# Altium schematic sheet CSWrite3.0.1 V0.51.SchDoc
size 609 x 431 mm; PageSetup: Record=PageOptions¦CenterHorizontal=True¦CenterVertical=True¦PrintScale=0.38¦XCorrection=1.00¦YCorrection=1.00¦PrintKind=2¦BorderSize=5000000¦LeftOffset=0¦BottomOffset=0¦Orientation=2¦PaperLength=1000¦PaperWidth=1000¦Scale=100¦PaperSource=7¦PrintQuality=-4¦MediaType=1¦DitherType=10¦PaperKind=A4¦PrintScaleMode=1
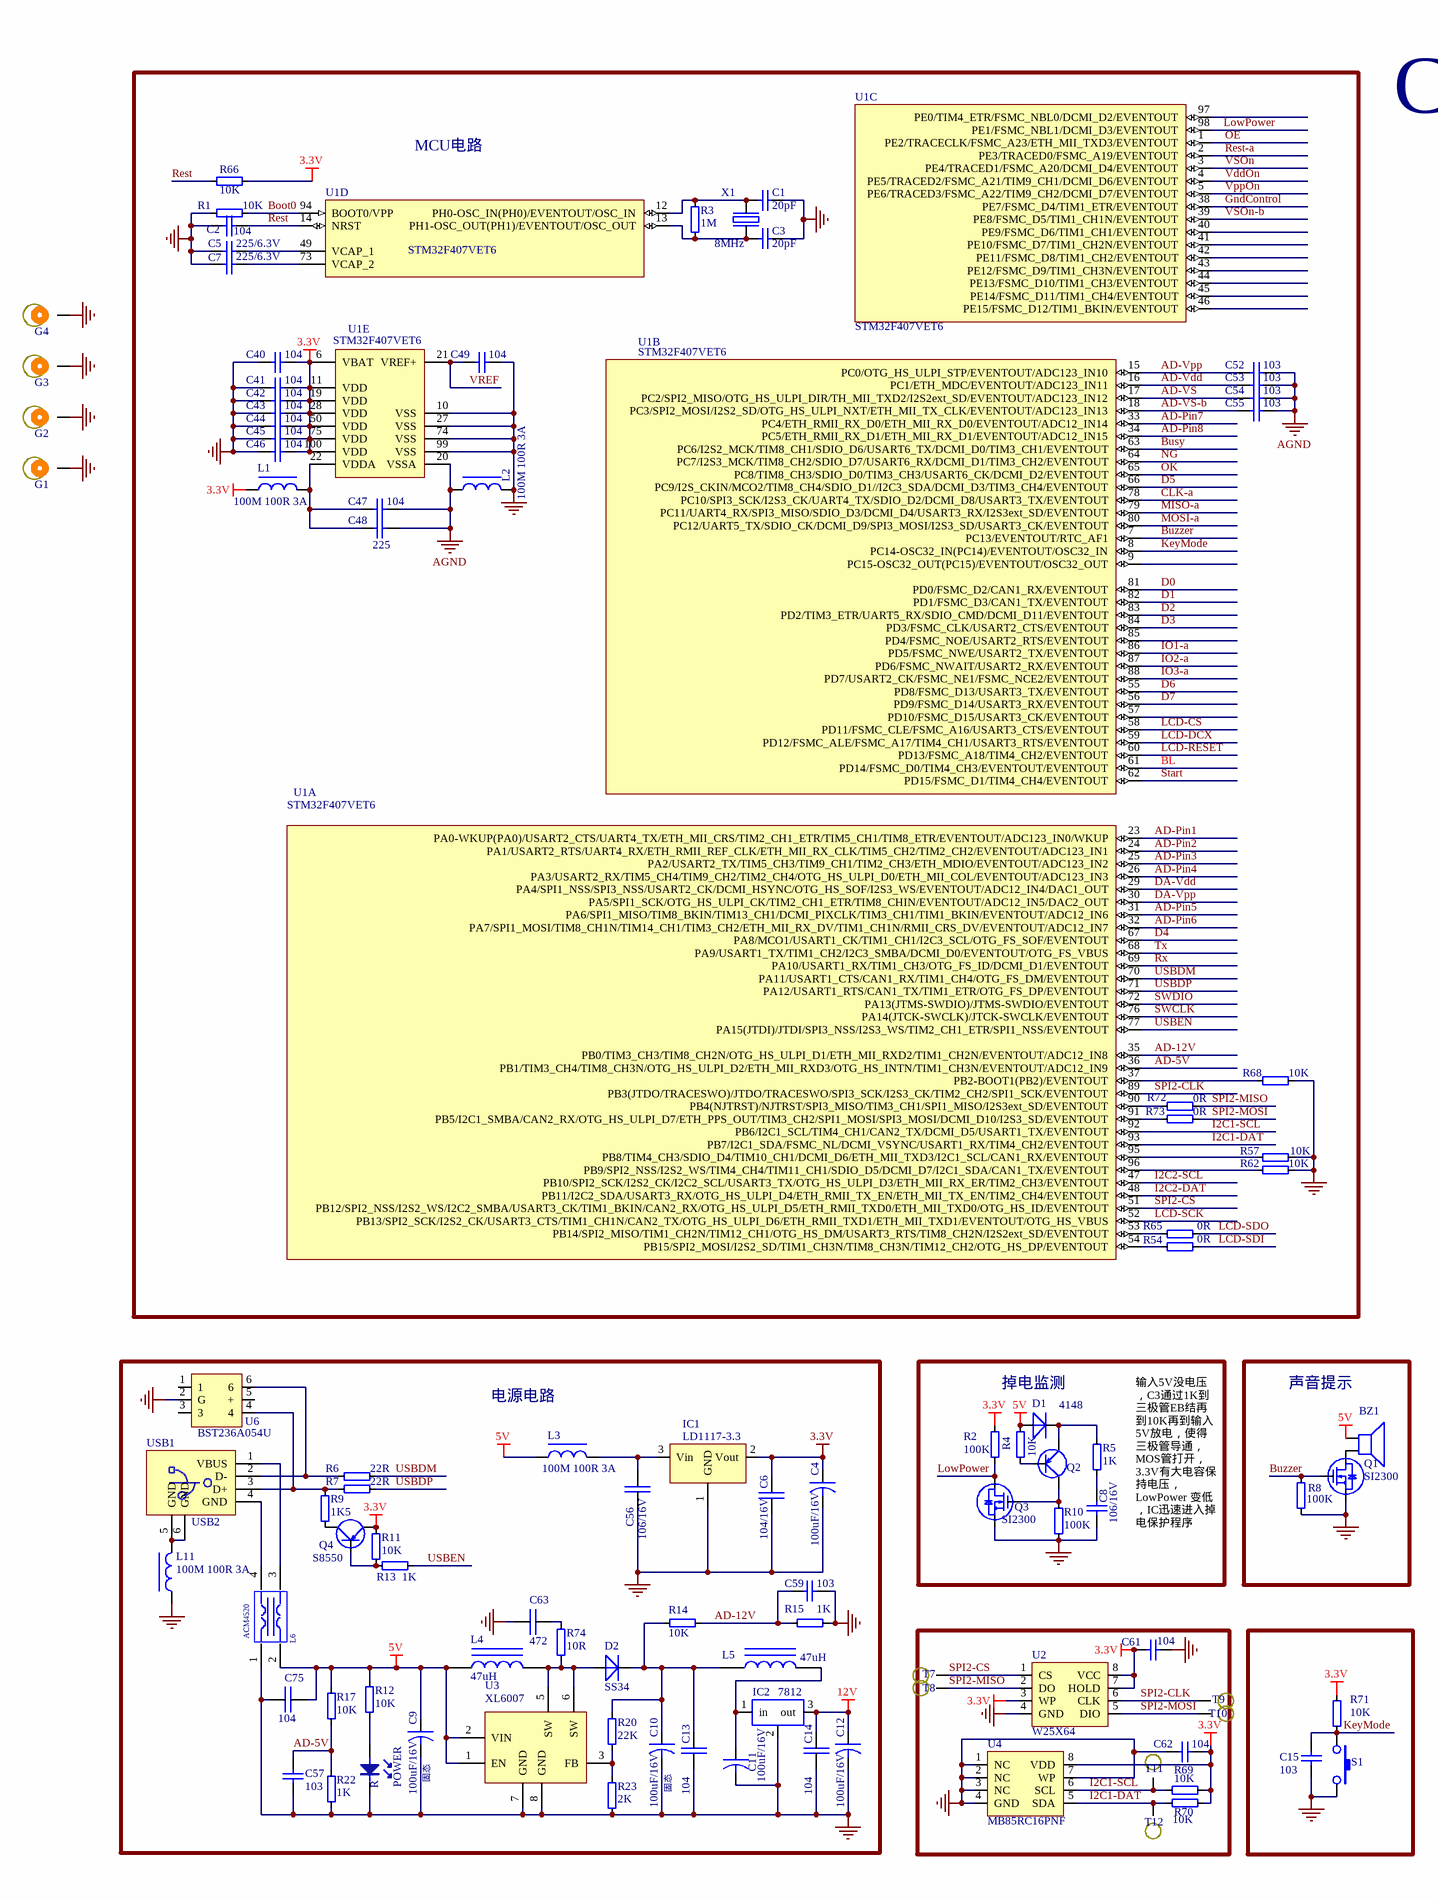
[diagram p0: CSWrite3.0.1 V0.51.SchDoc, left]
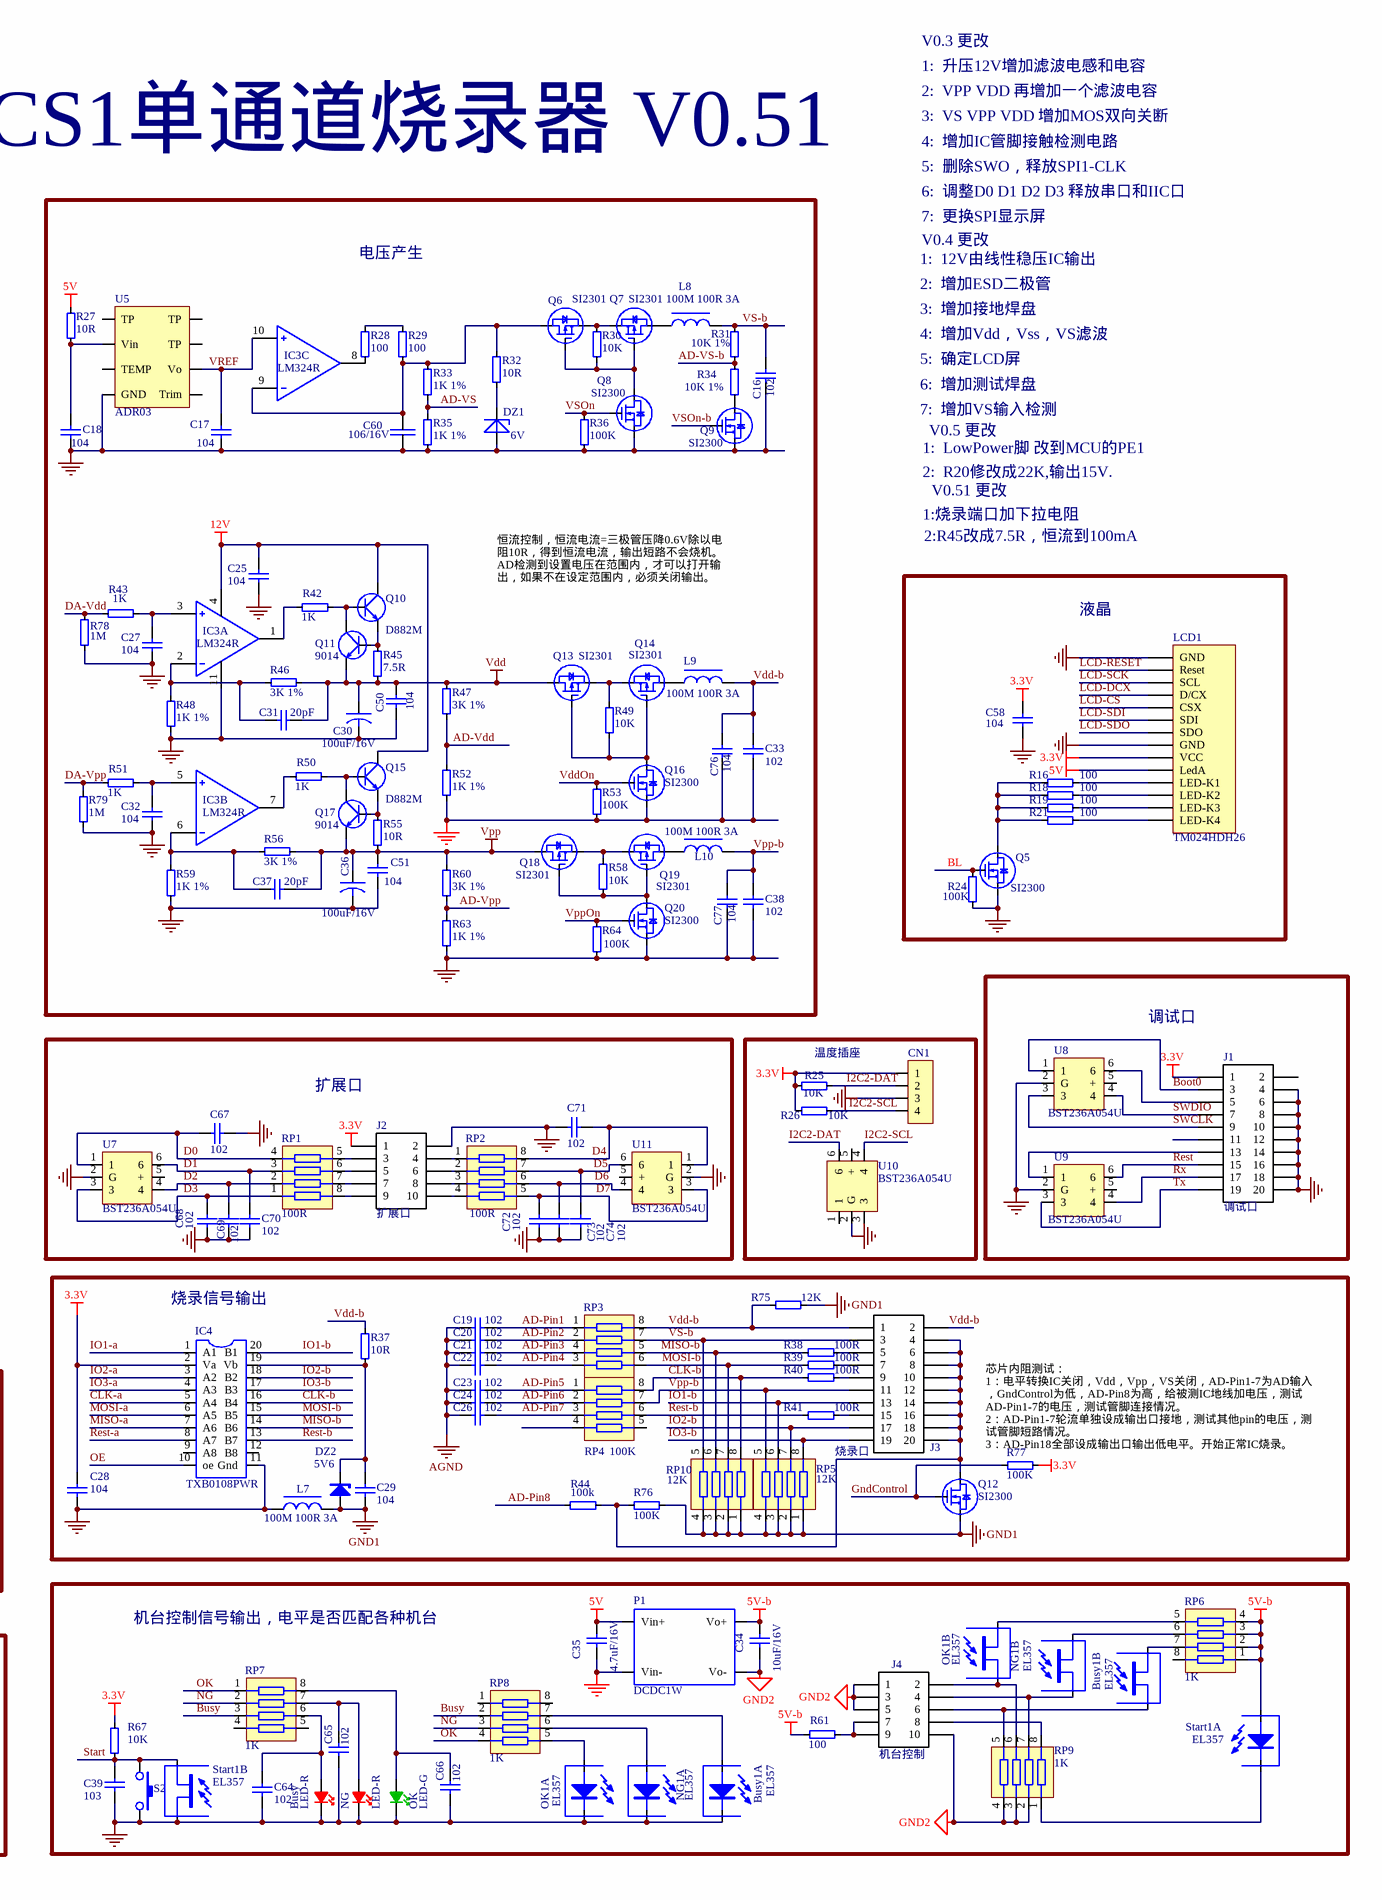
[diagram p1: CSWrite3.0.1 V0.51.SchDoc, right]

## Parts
Busy  LED-R  [LED05]
Busy1  EL357  [SOP-4]  (parts A,B of 2)
BZ1  BUZZER  [FMQ-9*5.5]  (value not drawn)
C1  20pF  [0603C]
C2  104  [0603C]
C3  20pF  [0603C]
C4  100uF/16V  [CAP-B]
C5  225/6.3V  [0603C]
C6  104/16V  [0603C]
C7  225/6.3V  [0603C]
C8  106/16V  [0603C]
C9  100uF/16V  [CB_8*11D5]
C10  100uF/16V  [CB_8*11D5]
C11  100uF/16V  [CB_8*11D5]
C12  100uF/16V  [CB_8*11D5]
C13  104  [0603C]
C14  104  [0603C]
C15  103  [0603C]
C16  102  [0603C]
C17  104  [0603C]
C18  104  [0603C]
C19  102  [0603C]
C20  102  [0603C]
C21  102  [0603C]
C22  102  [0603C]
C23  102  [0603C]
C24  102  [0603C]
C25  104  [0603C]
C26  102  [0603C]
C27  104  [0603C]
C28  104  [0603C]
C29  104  [0603C]
C30  100uF/16V  [CAP-B]
C31  20pF  [0603C]
C32  104  [0603C]
C33  102  [0603C]
C34  10uF/16V  [0603C]
C35  4.7uF/16V  [0603C]
C36  100uF/16V  [CAP-B]
C37  20pF  [0603C]
C38  102  [0603C]
C39  103  [0603C]
C40  104  [0603C]
C41  104  [0603C]
C42  104  [0603C]
C43  104  [0603C]
C44  104  [0603C]
C45  104  [0603C]
C46  104  [0603C]
C47  104  [0603C]
C48  225  [0603C]
C49  104  [0603C]
C50  104  [0603C]
C51  104  [0603C]
C52  103  [0603C]
C53  103  [0603C]
C54  103  [0603C]
C55  103  [0603C]
C56  106/16V  [0603C]
C57  103  [0603C]
C58  104  [0603C]
C59  103  [0603C]
C60  106/16V  [0603C]
C61  104  [0603C]
C62  104  [0603C]
C63  472  [0603C]
C64  102  [0603C]
C65  102  [0603C]
C66  102  [0603C]
C67  102  [0603C]
C68  102  [0603C]
C69  102  [0603C]
C70  102  [0603C]
C71  102  [0603C]
C72  102  [0603C]
C73  102  [0603C]
C74  102  [0603C]
C75  104  [0603C]
C76  104  [0603C]
C77  104  [0603C]
CN1  温度插座  [PH4AW_2D0]
D1  4148  [D1206]
D2  SS34  [D-SMA]
DZ1  6V  [D1206]
DZ2  5V6  [D1206]
G1  GND  [P1]  (value not drawn)
G2  GND  [P1]  (value not drawn)
G3  GND  [P1]  (value not drawn)
G4  GND  [P1]  (value not drawn)
IC1  LD1117-3.3  [SOT223]
IC2  7812  [TO252AA]
IC3  LM324R  [SOP14]  (parts A,B,C of 4)
IC4  TXB0108PWR  [TSSOP20]
J1  调试口  [DC_20P_W]
J2  扩展口  [IDC10-GZ]
J3  烧录口  [IDC20]
J4  机台控制
L1  100M 100R 3A  [0603]
L2  100M 100R 3A  [0603]
L3  100M 100R 3A  [0603]
L4  47uH  [L-SMD6.8*6.8]
L5  47uH  [L-SMD6.8*6.8]
L6  ACM4520  [L_6*7]
L7  100M 100R 3A  [0603]
L8  100M 100R 3A  [0603]
L9  100M 100R 3A  [0603]
L10  100M 100R 3A  [0603]
L11  100M 100R 3A  [0603]
LCD1  TM024HDH26  [TM024HDH26-V02]
NG  LED-R  [LED05]
NG1  EL357  [SOP-4]  (parts A,B of 2)
OK  LED-G  [LED05]
OK1  EL357  [SOP-4]  (parts A,B of 2)
P1  DCDC1W  [1WDC_DC-4]
POWER  R  [LED05]
Q1  SI2300  [SOT-23]
Q2  S8550  [SOT-23]  (value not drawn)
Q3  SI2300  [SOT-23]
Q4  S8550  [SOT23]
Q5  SI2300  [SOT-23]
Q6  SI2301  [SOT23]
Q7  SI2301  [SOT23]
Q8  SI2300  [SOT-23]
Q9  SI2300  [SOT-23]
Q10  D882M  [TO252AA]
Q11  9014  [SOT-23]
Q12  SI2300  [SOT-23]
Q13  SI2301  [SOT23]
Q14  SI2301  [SOT23]
Q15  D882M  [TO252AA]
Q16  SI2300  [SOT-23]
Q17  9014  [SOT-23]
Q18  SI2301  [SOT23]
Q19  SI2301  [SOT23]
Q20  SI2300  [SOT-23]
R1  10K  [0603]
R2  100K  [0603]
R3  1M  [0603]
R4  10K  [0603]
R5  1K  [0603]
R6  22R  [0603]
R7  22R  [0603]
R8  100K  [0603]
R9  1K5  [0603]
R10  100K  [0603]
R11  10K  [0603]
R12  10K  [0603]
R13  1K  [0603]
R14  10K  [0603]
R15  1K  [0603]
R16  100  [0603]
R17  10K  [0603]
R18  100  [0603]
R19  100  [0603]
R20  22K  [0603]
R21  100  [0603]
R22  1K  [0603]
R23  2K  [0603]
R24  100K  [0603]
R25  10K  [0603]
R26  10K  [0603]
R27  10R  [0603]
R28  100  [0603]
R29  100  [0603]
R30  10K  [0603]
R31  10K 1%  [0603]
R32  10R  [0603]
R33  1K 1%  [0603]
R34  10K 1%  [0603]
R35  1K 1%  [0603]
R36  100K  [0603]
R37  10R  [0603]
R38  100R  [0603]
R39  100R  [0603]
R40  100R  [0603]
R41  100R  [0603]
R42  1K  [0603]
R43  1K  [0603]
R44  100k  [0603]
R45  7.5R  [0603]
R46  3K 1%  [0603]
R47  3K 1%  [0603]
R48  1K 1%  [0603]
R49  10K  [0603]
R50  1K  [0603]
R51  1K  [0603]
R52  1K 1%  [0603]
R53  100K  [0603]
R54  0R  [0603]
R55  10R  [0603]
R56  3K 1%  [0603]
R57  10K  [0603]
R58  10K  [0603]
R59  1K 1%  [0603]
R60  3K 1%  [0603]
R61  100  [1206]
R62  10K  [0603]
R63  1K 1%  [0603]
R64  100K  [0603]
R65  0R  [0603]
R66  10K  [0603]
R67  10K  [0603]
R68  10K  [0603]
R69  10K  [0603]
R70  10K  [0603]
R71  10K  [0603]
R72  0R  [0603]
R73  0R  [0603]
R74  10R  [0603]
R75  12K  [0603]
R76  100K  [0603]
R77  100K  [0603]
R78  1M  [0603]
R79  1M  [0603]
RP1  100R  [0603_RX4]
RP2  100R  [0603_RX4]
RP3  100K  [0603_RX4]
RP4  100K  [0603_RX4]
RP5  12K  [0603_RX4]
RP6  1K  [0603_RX4]
RP7  1K  [0603_RX4]
RP8  1K  [0603_RX4]
RP9  1K  [0603_RX4]
RP10  12K  [0603_RX4]
S1  SW-PB  [SW6*6]  (value not drawn)
S2  SW-PB  [SW12*17_PB86]  (value not drawn)
Start1  EL357  [SOP-4]  (parts A,B of 2)
T7  GND  [P2]  (value not drawn)
T8  GND  [P2]  (value not drawn)
T9  GND  [P2]  (value not drawn)
T10  GND  [P2]  (value not drawn)
T11  GND  [P2]  (value not drawn)
T12  GND  [P2]  (value not drawn)
U1  STM32F407VET6  [LQFP100_V]  (parts A,B,C,D,E of 5)
U2  W25X64  [SO-08M]
U3  XL6007  [SO-8]
U4  MB85RC16PNF  [SO-08M]
U5  ADR03  [SOP8]
U6  BST236A054U  [SOT-23-6L]
U7  BST236A054U  [SOT-23-6L]
U8  BST236A054U  [SOT-23-6L]
U9  BST236A054U  [SOT-23-6L]
U10  BST236A054U  [SOT-23-6L]
U11  BST236A054U  [SOT-23-6L]
USB1  USB2  [USB2*2]
X1  8MHz  [ATX5*3.2]

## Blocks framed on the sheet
MCU电路: C1-C3 C5 C7 C40-C49 C52-C55 L1 L2 R1 R3 R54 R57 R62 R65 R66 R68 R72 R73 U1 X1
电压产生: C16-C18 C25 C27 C30-C33 C36-C38 C50 C51 C60 C76 C77 DZ1 IC3 L8-L10 Q6-Q11 Q13-Q20 R27-R36 R42 R43 R45-R53 R55 R56 R58-R60 R63 R64 R78 R79 U5
液晶: C58 LCD1 Q5 R16 R18 R19 R21 R24
调试口: J1 U8 U9
扩展口: C67-C74 J2 RP1 RP2 U7 U11
烧录信号输出: C19-C24 C26 C28 C29 DZ2 IC4 J3 L7 Q12 R37-R41 R44 R75-R77 RP3-RP5 RP10
电源电路: C4 C6 C9-C14 C56 C57 C59 C63 C75 D2 IC1 IC2 L3-L6 L11 POWER Q4 R6 R7 R9 R11-R15 R17 R20 R22 R23 R74 U3 U6 USB1
掉电监测: C8 D1 Q2 Q3 R2 R4 R5 R10
声音提示: BZ1 Q1 R8
机台控制信号输出，电平是否匹配各种机台: Busy Busy1 C34 C35 C39 C64-C66 J4 NG NG1 OK OK1 P1 R61 R67 RP6-RP9 S2 Start1

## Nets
3.3V: C4.1 C6.2 C28.1 C40.1 C41.1 C42.1 C43.1 C44.1 C45.1 C46.1 C58.1 C61.2 C62.1 CN1.1 IC1.2(Vout) IC4.2(Va) J1.1 J2.1 L1.1 LCD1.9(VCC) Q4.3(E) R2.2 R11.1 R25.2 R26.2 R66.2 R67.2 R69.1 R70.1 R71.2 R77.1 U1.6(VBAT) U1.11(VDD) U1.19(VDD) U1.28(VDD) U1.50(VDD) U1.75(VDD) U1.100(VDD) U2.3(WP) U2.7(HOLD) U2.8(VCC) U4.8(VDD)
5V: BZ1.1(+) C9.1 C35.2 C75.1 D1.1(A) L3.1 L4.1 L6.2 LCD1.10(LedA) P1.1(Vin+) R4.2 R12.2 R17.1 R27.2 U3.1(EN) U3.2(VIN)
5V-b: C34.2 P1.4(Vo+) R61.2 RP6.1 RP6.2 RP6.3 RP6.4 Start1.1(A)
12V: C12.1 C14.2 C25.2 IC2.3(out) IC3.4 Q10.2(C) Q15.2(C)
AGND: C19.1 C20.1 C21.1 C22.1 C23.1 C24.1 C26.1 C47.2 C48.2 C52.1 C53.1 C54.1 C55.1 L2.1 U1.20(VSSA)
GND: Busy.2 Busy1.2(K) C1.1 C2.1 C3.1 C4.2 C5.1 C6.1 C7.1 C8.1 C9.2 C10.2 C11.2 C12.2 C13.1 C14.1 C15.2 C16.2 C17.1 C18.1 C25.1 C27.1 C28.2 C30.2 C32.1 C33.1 C35.1 C36.2 C38.1 C39.2 C40.2 C41.2 C42.2 C43.2 C44.2 C45.2 C46.2 C49.1 C50.1 C51.1 C56.1 C57.2 C58.2 C59.2 C60.1 C61.1 C62.2 C63.2 C64.1 C65.1 C66.1 C67.1 C68.1 C69.1 C70.1 C71.2 C72.1 C73.1 C74.1 C75.2 C76.2 C77.2 CN1.3 DZ1.1(A) G1.1 G2.1 G3.1 G4.1 IC1.1(GND) IC2.2 IC3.11 IC4.11(Gnd) J1.4 J1.6 J1.8 J1.10 J1.12 J1.14 J1.16 J1.18 J1.20 J2.2 L2.2 L6.1 L7.1 L11.1 LCD1.1(GND) LCD1.8(GND) NG.2 NG1.2(K) OK.2 OK1.2(K) P1.2(Vin-) POWER.2(K) Q1.3(S) Q3.3(S) Q5.3(S) Q8.3(S) Q9.3(S) Q16.3(S) Q20.3(S) R1.1 R8.2 R10.1 R15.2 R22.2 R23.2 R24.2 R35.2 R36.1 R48.1 R52.2 R53.1 R57.1 R59.1 R62.1 R63.2 R64.1 R68.1 R78.1 R79.1 S1.1 S2.1 Start1.4(C) U1.10(VSS) U1.27(VSS) U1.74(VSS) U1.99(VSS) U2.4(GND) U3.7(GND) U3.8(GND) U4.1(NC) U4.2(NC) U4.3(NC) U4.4(GND) U4.7(WP) U5.4(GND) U6.2(G) U7.2(G) U8.2(G) U9.2(G) U10.2(G) U11.2(G)
GND1: C29.2 DZ2.1(A) L7.2 Q12.3(S) R75.2 R76.1 RP5.1 RP5.2 RP5.3 RP5.4 RP10.1 RP10.2 RP10.3 RP10.4
GND2: C34.1 J4.1 J4.3 J4.5 J4.10 P1.3(Vo-) RP9.2 RP9.3 RP9.4
Vdd: C30.1 C31.2 C50.2 Q11.3(E) Q13.2(D) R45.2 R46.2 R47.1
Vpp: C36.1 C37.2 C51.2 Q17.3(E) Q18.2(D) R55.2 R56.2 R60.1
AD-5V: C57.1 R17.2 R22.1 U1.36(PB1/TIM3_CH4/TIM8_CH3N/OTG_HS_ULPI_D2/ETH_MII_RXD3/OTG_HS_INTN/TIM1_CH3N/EVENTOUT/ADC12_IN9)
AD-12V: C59.1 R14.2 R15.1 U1.35(PB0/TIM3_CH3/TIM8_CH2N/OTG_HS_ULPI_D1/ETH_MII_RXD2/TIM1_CH2N/EVENTOUT/ADC12_IN8)
AD-Pin1: C19.2 RP3.1 U1.23(PA0-WKUP(PA0)/USART2_CTS/UART4_TX/ETH_MII_CRS/TIM2_CH1_ETR/TIM5_CH1/TIM8_ETR/EVENTOUT/ADC123_IN0/WKUP)
AD-Pin2: C20.2 RP3.2 U1.24(PA1/USART2_RTS/UART4_RX/ETH_RMII_REF_CLK/ETH_MII_RX_CLK/TIM5_CH2/TIM2_CH2/EVENTOUT/ADC123_IN1)
AD-Pin3: C21.2 RP3.4 U1.25(PA2/USART2_TX/TIM5_CH3/TIM9_CH1/TIM2_CH3/ETH_MDIO/EVENTOUT/ADC123_IN2)
AD-Pin4: C22.2 RP3.3 U1.26(PA3/USART2_RX/TIM5_CH4/TIM9_CH2/TIM2_CH4/OTG_HS_ULPI_D0/ETH_MII_COL/EVENTOUT/ADC123_IN3)
AD-Pin5: C23.2 RP4.1 U1.31(PA6/SPI1_MISO/TIM8_BKIN/TIM13_CH1/DCMI_PIXCLK/TIM3_CH1/TIM1_BKIN/EVENTOUT/ADC12_IN6)
AD-Pin6: C24.2 RP4.2 U1.32(PA7/SPI1_MOSI/TIM8_CH1N/TIM14_CH1/TIM3_CH2/ETH_MII_RX_DV/TIM1_CH1N/RMII_CRS_DV/EVENTOUT/ADC12_IN7)
AD-Pin7: C26.2 RP4.3 U1.33(PC4/ETH_RMII_RX_D0/ETH_MII_RX_D0/EVENTOUT/ADC12_IN14)
AD-Pin8: R44.1 U1.34(PC5/ETH_RMII_RX_D1/ETH_MII_RX_D1/EVENTOUT/ADC12_IN15)
AD-Vdd: C53.2 R47.2 R52.1 U1.16(PC1/ETH_MDC/EVENTOUT/ADC123_IN11)
AD-Vpp: C52.2 R60.2 R63.1 U1.15(PC0/OTG_HS_ULPI_STP/EVENTOUT/ADC123_IN10)
AD-VS: C54.2 R33.2 R35.1 U1.17(PC2/SPI2_MISO/OTG_HS_ULPI_DIR/TH_MII_TXD2/I2S2ext_SD/EVENTOUT/ADC123_IN12)
AD-VS-b: C55.2 R31.2 R34.1 U1.18(PC3/SPI2_MOSI/I2S2_SD/OTG_HS_ULPI_NXT/ETH_MII_TX_CLK/EVENTOUT/ADC123_IN13)
BL: Q5.1(G) R24.1 U1.61(PD14/FSMC_D0/TIM4_CH3/EVENTOUT/EVENTOUT)
Boot0: J1.3 R1.2 U1.94(BOOT0/VPP) U8.1
Busy: RP7.3 RP8.2 U1.63(PC6/I2S2_MCK/TIM8_CH1/SDIO_D6/USART6_TX/DCMI_D0/TIM3_CH1/EVENTOUT)
Buzzer: Q1.1(G) R8.1 U1.7(PC13/EVENTOUT/RTC_AF1)
CLK-a: IC4.5(A4) U1.78(PC10/SPI3_SCK/I2S3_CK/UART4_TX/SDIO_D2/DCMI_D8/USART3_TX/EVENTOUT)
CLK-b: IC4.16(B4) R40.1 RP4.8 RP10.8
D0: C67.2 RP1.4 U1.81(PD0/FSMC_D2/CAN1_RX/EVENTOUT) U7.1
D1: C70.2 RP1.3 U1.82(PD1/FSMC_D3/CAN1_TX/EVENTOUT) U7.6
D2: C69.2 RP1.2 U1.83(PD2/TIM3_ETR/UART5_RX/SDIO_CMD/DCMI_D11/EVENTOUT) U7.4
D3: C68.2 RP1.1 U1.84(PD3/FSMC_CLK/USART2_CTS/EVENTOUT) U7.3
D4: C71.1 RP2.8 U1.67(PA8/MCO1/USART1_CK/TIM1_CH1/I2C3_SCL/OTG_FS_SOF/EVENTOUT) U11.1
D5: C74.2 RP2.7 U1.66(PC9/I2S_CKIN/MCO2/TIM8_CH4/SDIO_D1//I2C3_SDA/DCMI_D3/TIM3_CH4/EVENTOUT) U11.6
D6: C73.2 RP2.6 U1.55(PD8/FSMC_D13/USART3_TX/EVENTOUT) U11.4
D7: C72.2 RP2.5 U1.56(PD9/FSMC_D14/USART3_RX/EVENTOUT) U11.3
DA-Vdd: R43.1 R78.2 U1.29(PA4/SPI1_NSS/SPI3_NSS/USART2_CK/DCMI_HSYNC/OTG_HS_SOF/I2S3_WS/EVENTOUT/ADC12_IN4/DAC1_OUT)
DA-Vpp: R51.1 R79.2 U1.30(PA5/SPI1_SCK/OTG_HS_ULPI_CK/TIM2_CH1_ETR/TIM8_CHIN/EVENTOUT/ADC12_IN5/DAC2_OUT)
GndControl: Q12.1(G) R77.2 U1.38(PE7/FSMC_D4/TIM1_ETR/EVENTOUT)
I2C1-DAT: R70.2 T12.1 U1.93(PB7/I2C1_SDA/FSMC_NL/DCMI_VSYNC/USART1_RX/TIM4_CH2/EVENTOUT) U4.5(SDA)
I2C1-SCL: R69.2 T11.1 U1.92(PB6/I2C1_SCL/TIM4_CH1/CAN2_TX/DCMI_D5/USART1_TX/EVENTOUT) U4.6(SCL)
I2C2-DAT: CN1.2 R25.1 U1.48(PB11/I2C2_SDA/USART3_RX/OTG_HS_ULPI_D4/ETH_RMII_TX_EN/ETH_MII_TX_EN/TIM2_CH4/EVENTOUT) U10.6
I2C2-SCL: CN1.4 R26.1 U1.47(PB10/SPI2_SCK/I2S2_CK/I2C2_SCL/USART3_TX/OTG_HS_ULPI_D3/ETH_MII_RX_ER/TIM2_CH3/EVENTOUT) U10.4
IO1-a: IC4.1(A1) U1.86(PD5/FSMC_NWE/USART2_TX/EVENTOUT)
IO1-b: IC4.20(B1) J3.13 RP5.6
IO2-a: IC4.3(A2) U1.87(PD6/FSMC_NWAIT/USART2_RX/EVENTOUT)
IO2-b: IC4.18(B2) J3.17 RP5.7
IO3-a: IC4.4(A3) U1.88(PD7/USART2_CK/FSMC_NE1/FSMC_NCE2/EVENTOUT)
IO3-b: IC4.17(B3) J3.19 RP5.8
KeyMode: C15.1 R71.1 S1.2 U1.8(PC14-OSC32_IN(PC14)/EVENTOUT/OSC32_IN)
LCD-CS: LCD1.5(CSX) U1.58(PD11/FSMC_CLE/FSMC_A16/USART3_CTS/EVENTOUT)
LCD-DCX: LCD1.4(D/CX) U1.59(PD12/FSMC_ALE/FSMC_A17/TIM4_CH1/USART3_RTS/EVENTOUT)
LCD-RESET: LCD1.2(Reset) U1.60(PD13/FSMC_A18/TIM4_CH2/EVENTOUT)
LCD-SCK: LCD1.3(SCL) U1.52(PB13/SPI2_SCK/I2S2_CK/USART3_CTS/TIM1_CH1N/CAN2_TX/OTG_HS_ULPI_D6/ETH_RMII_TXD1/ETH_MII_TXD1/EVENTOUT/OTG_HS_VBUS)
LCD-SDI: LCD1.6(SDI) R54.1
LCD-SDO: LCD1.7(SDO) R65.1
LowPower: Q3.2(D) R2.1 U1.98(PE1/FSMC_NBL1/DCMI_D3/EVENTOUT)
MISO-a: IC4.7(A6) U1.79(PC11/UART4_RX/SPI3_MISO/SDIO_D3/DCMI_D4/USART3_RX/I2S3ext_SD/EVENTOUT)
MISO-b: IC4.14(B6) R38.1 RP3.5 RP10.6
MOSI-a: IC4.6(A5) U1.80(PC12/UART5_TX/SDIO_CK/DCMI_D9/SPI3_MOSI/I2S3_SD/USART3_CK/EVENTOUT)
MOSI-b: IC4.15(B5) R39.1 RP3.6 RP10.7
NG: RP7.2 RP8.3 U1.64(PC7/I2S3_MCK/TIM8_CH2/SDIO_D7/USART6_RX/DCMI_D1/TIM3_CH2/EVENTOUT)
OE: IC4.10(oe) U1.1(PE2/TRACECLK/FSMC_A23/ETH_MII_TXD3/EVENTOUT)
OK: RP7.1 RP8.4 U1.65(PC8/TIM8_CH3/SDIO_D0/TIM3_CH3/USART6_CK/DCMI_D2/EVENTOUT)
Rest: C2.2 J1.15 R66.1 U1.14(NRST) U9.6
Rest-a: IC4.8(A7) U1.2(PE3/TRACED0/FSMC_A19/EVENTOUT)
Rest-b: IC4.13(B7) R41.1 RP4.6
Rx: J1.17 U1.69(PA10/USART1_RX/TIM1_CH3/OTG_FS_ID/DCMI_D1/EVENTOUT) U9.4
SPI2-CLK: T9.1 U1.89(PB3(JTDO/TRACESWO)/JTDO/TRACESWO/SPI3_SCK/I2S3_CK/TIM2_CH2/SPI1_SCK/EVENTOUT) U2.6(CLK)
SPI2-CS: T7.1 U1.51(PB12/SPI2_NSS/I2S2_WS/I2C2_SMBA/USART3_CK/TIM1_BKIN/CAN2_RX/OTG_HS_ULPI_D5/ETH_RMII_TXD0/ETH_MII_TXD0/OTG_HS_ID/EVENTOUT) U2.1(CS)
SPI2-MISO: R72.1 T8.1 U2.2(DO)
SPI2-MOSI: R73.1 T10.1 U2.5(DIO)
Start: C39.1 R67.1 S2.2 Start1.3(E) U1.62(PD15/FSMC_D1/TIM4_CH4/EVENTOUT)
SWCLK: J1.9 U1.76(PA14(JTCK-SWCLK)/JTCK-SWCLK/EVENTOUT) U8.3
SWDIO: J1.7 U1.72(PA13(JTMS-SWDIO)/JTMS-SWDIO/EVENTOUT) U8.4
Tx: J1.19 U1.68(PA9/USART1_TX/TIM1_CH2/I2C3_SMBA/DCMI_D0/EVENTOUT/OTG_FS_VBUS) U9.3
USBDM: R7.1 U1.70(PA11/USART1_CTS/CAN1_RX/TIM1_CH4/OTG_FS_DM/EVENTOUT)
USBDP: R6.1 U1.71(PA12/USART1_RTS/CAN1_TX/TIM1_ETR/OTG_FS_DP/EVENTOUT)
USBEN: R13.2 U1.77(PA15(JTDI)/JTDI/SPI3_NSS/I2S3_WS/TIM2_CH1_ETR/SPI1_NSS/EVENTOUT)
Vdd-b: C33.2 C76.1 J3.1 J3.2 L9.2 R37.1 R75.1 RP3.8
VddOn: Q16.1(G) R53.2 U1.4(PE5/TRACED2/FSMC_A21/TIM9_CH1/DCMI_D6/EVENTOUT)
Vpp-b: C38.2 C77.1 J3.11 L10.2 RP4.7 RP5.5
VppOn: Q20.1(G) R64.2 U1.5(PE6/TRACED3/FSMC_A22/TIM9_CH2/DCMI_D7/EVENTOUT)
VREF: C17.2 C49.2 IC3.10 U1.21(VREF+) U5.6(Vo)
VS-b: C16.1 J3.3 L8.2 R31.1 RP3.7 RP10.5
VSOn: Q8.1(G) R36.2 U1.3(PE4/TRACED1/FSMC_A20/DCMI_D4/EVENTOUT)
VSOn-b: Q9.1(G) U1.39(PE8/FSMC_D5/TIM1_CH1N/EVENTOUT)
NetBusy1_1: Busy1.1(A) RP8.7
NetBusy1_3: Busy1.3(E) J4.6 RP9.5
NetBusy1_4: Busy1.4(C) RP6.7
NetBusy_1: Busy.1 C64.2 RP7.6
NetBZ1_2: BZ1.2(-) Q1.2(D)
NetC1_2: C1.2 R3.2 U1.12(PH0-OSC_IN(PH0)/EVENTOUT/OSC_IN) X1.2
NetC3_2: C3.2 R3.1 U1.13(PH1-OSC_OUT(PH1)/EVENTOUT/OSC_OUT) X1.1
NetC5_2: C5.2 U1.49(VCAP_1)
NetC7_2: C7.2 U1.73(VCAP_2)
NetC8_2: C8.2 R5.1
NetC10_1: C10.1 C13.2 D2.2(K) L5.1 R14.1 R20.1
NetC11_1: C11.1 IC2.1(in) L5.2
NetC18_2: C18.2 R27.1 U5.2(Vin)
NetC27_2: C27.2 IC3.3 R43.2
NetC29_1: C29.1 DZ2.2(K) IC4.19(Vb) R37.2
NetC31_1: C31.1 IC3.2 R46.1 R48.2
NetC32_2: C32.2 IC3.5 R51.2
NetC37_1: C37.1 IC3.6 R56.1 R59.2
NetC47_1: C47.1 C48.1 L1.2 U1.22(VDDA)
NetC56_2: C56.2 IC1.3(Vin) L3.2
NetC60_2: C60.2 IC3.9 Q6.2(D) R29.1 R32.1 R33.1
NetC63_1: C63.1 R74.1
NetC65_2: C65.2 NG.1 RP7.7
NetC66_2: C66.2 OK.1 RP7.8
NetD1_2: D1.2(K) Q2.3(E) R5.2
NetD2_1: D2.1(A) L4.2 R74.2 U3.5(SW) U3.6(SW)
NetDZ1_2: DZ1.2(K) R32.2
NetIC3_1: IC3.1 R42.1
NetIC3_7: IC3.7 R50.1
NetIC3_8: IC3.8 R28.1
NetJ1_5: J1.5 U8.6
NetJ1_13: J1.13 U9.1
NetJ2_3: J2.3 RP1.5
NetJ2_4: J2.4 RP2.1
NetJ2_5: J2.5 RP1.6
NetJ2_6: J2.6 RP2.2
NetJ2_7: J2.7 RP1.7
NetJ2_8: J2.8 RP2.3
NetJ2_9: J2.9 RP1.8
NetJ2_10: J2.10 RP2.4
NetJ3_4: J3.4 J3.6 J3.8 J3.10 J3.12 J3.14 J3.16 J3.18 J3.20 Q12.2(D) R44.2 R76.2
NetJ3_5: J3.5 R38.2
NetJ3_7: J3.7 R39.2
NetJ3_9: J3.9 R40.2
NetJ3_15: J3.15 R41.2
NetJ4_2: J4.2 OK1.3(E) RP9.6
NetJ4_4: J4.4 NG1.3(E) RP9.7
NetJ4_7: J4.7 J4.9 R61.1
NetJ4_8: J4.8 RP9.8
NetL6_3: L6.3 USB1.1(VBUS)
NetL6_4: L6.4 USB1.4(GND)
NetL8_1: L8.1 Q7.2(D)
NetL9_1: L9.1 Q14.2(D)
NetL10_1: L10.1 Q19.2(D)
NetL11_2: L11.2 USB1.5(GND) USB1.6(GND)
NetLCD1_11: LCD1.11(LED-K1) R16.2
NetLCD1_12: LCD1.12(LED-K2) R18.2
NetLCD1_13: LCD1.13(LED-K3) R19.2
NetLCD1_14: LCD1.14(LED-K4) R21.2
NetNG1_1: NG1.1(A) RP8.6
NetNG1_4: NG1.4(C) RP6.6
NetOK1_1: OK1.1(A) RP8.5
NetOK1_4: OK1.4(C) RP6.5
NetPOWER_1: POWER.1(A) R12.1
NetQ2_1: Q2.1(B) R4.1
NetQ2_2: Q2.2(C) Q3.1(G) R10.2
NetQ4_1: Q4.1(B) R11.2 R13.1
NetQ4_2: Q4.2(C) R9.2
NetQ5_2: Q5.2(D) R16.1 R18.1 R19.1 R21.1
NetQ6_1: Q6.1(G) Q7.1(G) Q8.2(D) R30.1
NetQ6_3: Q6.3(S) Q7.3(S) R30.2
NetQ9_2: Q9.2(D) R34.2
NetQ10_1: Q10.1(B) Q11.2(C) R42.2
NetQ10_3: Q10.3(E) Q11.1(B) R45.1
NetQ13_1: Q13.1(G) Q14.1(G) Q16.2(D) R49.1
NetQ13_3: Q13.3(S) Q14.3(S) R49.2
NetQ15_1: Q15.1(B) Q17.2(C) R50.2
NetQ15_3: Q15.3(E) Q17.1(B) R55.1
NetQ18_1: Q18.1(G) Q19.1(G) Q20.2(D) R58.1
NetQ18_3: Q18.3(S) Q19.3(S) R58.2
NetR6_2: R6.2 R9.1 U6.4 USB1.3(D+)
NetR7_2: R7.2 U6.6 USB1.2(D-)
NetR20_2: R20.2 R23.1 U3.3(FB)
NetR28_2: R28.2 R29.2
NetR54_2: R54.2 U1.54(PB15/SPI2_MOSI/I2S2_SD/TIM1_CH3N/TIM8_CH3N/TIM12_CH2/OTG_HS_DP/EVENTOUT)
NetR57_2: R57.2 U1.95(PB8/TIM4_CH3/SDIO_D4/TIM10_CH1/DCMI_D6/ETH_MII_TXD3/I2C1_SCL/CAN1_RX/EVENTOUT)
NetR62_2: R62.2 U1.96(PB9/SPI2_NSS/I2S2_WS/TIM4_CH4/TIM11_CH1/SDIO_D5/DCMI_D7/I2C1_SDA/CAN1_TX/EVENTOUT)
NetR65_2: R65.2 U1.53(PB14/SPI2_MISO/TIM1_CH2N/TIM12_CH1/OTG_HS_DM/USART3_RTS/TIM8_CH2N/I2S2ext_SD/EVENTOUT)
NetR68_2: R68.2 U1.37(PB2-BOOT1(PB2)/EVENTOUT)
NetR72_2: R72.2 U1.90(PB4(NJTRST)/NJTRST/SPI3_MISO/TIM3_CH1/SPI1_MISO/I2S3ext_SD/EVENTOUT)
NetR73_2: R73.2 U1.91(PB5/I2C1_SMBA/CAN2_RX/OTG_HS_ULPI_D7/ETH_PPS_OUT/TIM3_CH2/SPI1_MOSI/SPI3_MOSI/DCMI_D10/I2S3_SD/EVENTOUT)
NetRP9_1: RP9.1 Start1.2(K)

Not connected (* = marked no-connect by the designer): IC4 9(A8) 12(B8); J1 2 11; RP4 4 5; RP6 8; RP7 4 5; RP8 1 8; U1 9(PC15-OSC32_OUT(PC15)/EVENTOUT/OSC32_OUT) 40(PE9/FSMC_D6/TIM1_CH1/EVENTOUT) 41(PE10/FSMC_D7/TIM1_CH2N/EVENTOUT) 42(PE11/FSMC_D8/TIM1_CH2/EVENTOUT) 43(PE12/FSMC_D9/TIM1_CH3N/EVENTOUT) 44(PE13/FSMC_D10/TIM1_CH3/EVENTOUT) 45(PE14/FSMC_D11/TIM1_CH4/EVENTOUT) 46(PE15/FSMC_D12/TIM1_BKIN/EVENTOUT) 57(PD10/FSMC_D15/USART3_CK/EVENTOUT) 85(PD4/FSMC_NOE/USART2_RTS/EVENTOUT) 97(PE0/TIM4_ETR/FSMC_NBL0/DCMI_D2/EVENTOUT); U5 1(TP) 3(TEMP) 5(Trim) 7(TP) 8(TP); U6 1 3 5(+); U7 5(+); U8 5(+); U9 5(+); U10 1 3 5(+); U11 5(+)

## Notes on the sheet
- V0.3 更改
- 1:  升压12V增加滤波电感和电容
- 2:  VPP VDD 再增加一个滤波电容
- 3:  VS VPP VDD 增加MOS双向关断
- CS1单通道烧录器 V0.51
- 4:  增加IC管脚接触检测电路
- 5:  删除SWO，释放SPI1-CLK
- 6:  调整D0 D1 D2 D3 释放串口和IIC口
- 7:  更换SPI显示屏
- V0.4 更改
- 1:  12V由线性稳压IC输出
- 2:  增加ESD二极管
- 3:  增加接地焊盘
- 4:  增加Vdd，Vss，VS滤波
- 5:  确定LCD屏
- 6:  增加测试焊盘
- 7:  增加VS输入检测
- V0.5 更改
- 1:  LowPower脚 改到MCU的PE1
- 2:  R20修改成22K,输出15V.
- V0.51 更改
- 1:烧录端口加下拉电阻
- 2:R45改成7.5R，恒流到100mA
- 恒流控制，恒流电流=三极管压降0.6V除以电阻10R，得到恒流电流，输出短路不会烧机。AD检测到设置电压在范围内，才可以打开输出，如果不在设定范围内，必须关闭输出。
- (near R77) 芯片内阻测试：
  1：电平转换IC关闭，Vdd，Vpp，VS关闭，AD-Pin1-7为AD输入，GndControl为低，AD-Pin8为高，给被测IC地线加电压，测试AD-Pin1-7的电压，测试管脚连接情况。
  2：AD-Pin1-7轮流单独设成输出口接地，测试其他pin的电压，测试管脚短路情况。
  3：AD-Pin18全部设成输出口输出低电平。开始正常IC烧录。
- 输入5V没电压，C3通过1K到三极管EB结再到10K再到输入5V放电，使得三极管导通，MOS管打开，3.3V有大电容保持电压，LowPower 变低，IC迅速进入掉电保护程序
- (near C9) 固态
- 固态

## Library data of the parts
Busy NG = LEDR
Busy1 NG1 OK1 Start1 = MOS光耦
BZ1 = Speaker
C1-C3 C5-C8 C13-C29 C31-C35 C37-C77 = CAP: 无极电容
C4 C9-C12 C30 C36 = CAPACITOR
CN1 = CON4: 接插件
D1 D2 = D: 二极管
DZ1 = DZ_s: 贴片稳压管
DZ2 = DZ: 稳压二极管
G1-G4 T7-T12 = J1
IC1 = LM1117
IC2 = 7805: 三端稳压
IC3 = LM324: 运放IC
IC4 = IC20Pin
J1 J3 = Con10x2
J2 J4 = Con5x2
L1-L3 L7-L11 = L1
L4 L5 = INDUCTOR IRON
L6 = ACP3225: PCB DECAL: COIL_ACM4520
LCD1 = SIP14: jointbar
OK = LEDG
P1 = 1WDC_DC
POWER = LED-B
Q1 Q3 Q5 Q8 Q9 Q12 Q16 Q20 = MOSFET N: 场效应管
Q2 Q4 = PNP1: 三极管
Q6 Q7 Q13 Q14 Q18 Q19 = PMOS: 场效应管
Q10 Q11 Q15 Q17 = NPN1: 三极管
R1-R19 R21 R22 R24-R73 R75-R79 = R: 电阻
R20 R23 R74 = RES: 电阻
RP1-RP10 = RP-4
U1 = STM32F407VET6: ARM Cortex-M4 32b MCU+FPU, 210DMIP, 512 kB Flash, 192+4 kB RAM, Camera, 82 I/Os, 100-pin LQFP, -40 to +85癈, Tray; Internal RAM: 192kB; Operating Frequency (Processor Speed): 168MHz; A/D Converter: 16x12-bit; D/A Converter: 2x12-bit; 16-bit Timers (IC/OC/PWM): 12x16-bit(24/24/30); 32-bit Timer (IC/OC/PWM): 2x32-bit (8/8/8); Other Timer Functions: 2xWDG, RTC, 24-bit down counter; Serial Interface: 3xSPI/2xI2S/2xI2C/3xUSART(IrDa, ISO7816)/3xUART/2xUSB OTG FS/HS, 2xCAN/Ethernet MAC10/100, SDIO
U2 U4 = W25X16
U3 = XL4007
U5 = AD680AR
U6-U11 = 6PIN
X1 = ATX: 晶体振荡器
